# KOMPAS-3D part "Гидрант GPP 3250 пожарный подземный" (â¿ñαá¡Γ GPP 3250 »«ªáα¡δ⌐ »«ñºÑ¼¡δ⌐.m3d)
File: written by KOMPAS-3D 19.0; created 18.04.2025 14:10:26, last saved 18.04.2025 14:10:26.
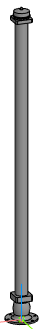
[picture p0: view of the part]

Document properties: Полное имя файла: E:\Dendor Работа Сачек\3D для проекитирвщиков\11.1 Тип GPP. Гидрант пожарный подземный\stp_Тип GPP. 750-6000 Гидрант пожарный подземный\Гидрант GPP 3250 пожарный подземный.m3d

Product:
- Part/product: Гидрант GPP 3250 пожарный подземный

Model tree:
1. Операция без истории:1  (labels: Гидрант GPP 3250 пожарный подземный)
